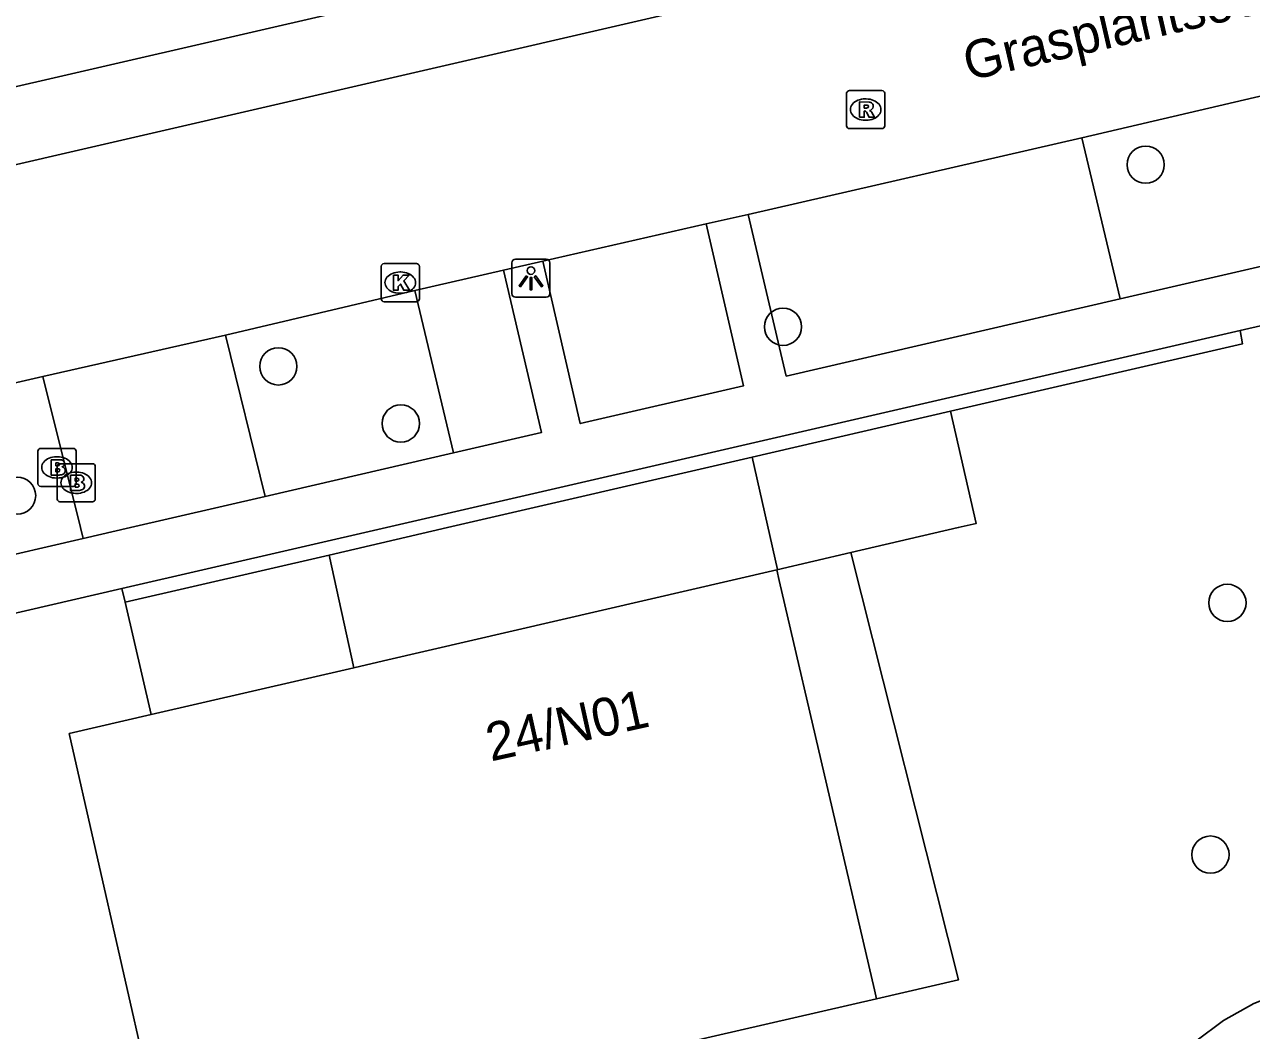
# Model space of a CAD drawing. Extents: x 156414 to 157775, y 382335 to 383765.
# Drawn here: x 156810.03 to 156842.21, y 382736.81 to 382763.2 of the extents above; entities that cross this region are included whole.
import ezdxf

# ---------------------------------------------------------------- set-up
doc = ezdxf.new("R2010")
doc.units = 0
for name, color, linetype in [('IMGEO_Boom', 7, 'Continuous'), ('IMGEO_Brandkraan', 7, 'Continuous'), ('IMGEO_Groenvoorziening', 7, 'Continuous'), ('IMGEO_Kolk', 7, 'Continuous'), ('IMGEO_Lichtpunt', 7, 'Continuous'), ('IMGEO_Lijnafwatering', 7, 'Continuous'), ('IMGEO_Muur', 7, 'Continuous'), ('IMGEO_Openbare_ruimte_label', 7, 'Continuous'), ('IMGEO_Pand', 7, 'Continuous'), ('IMGEO_Pand_nummerreeks', 7, 'Continuous'), ('IMGEO_Parkeervlak_open', 7, 'Continuous'), ('IMGEO_Rijbaan_lokaal_gesloten', 7, 'Continuous'), ('IMGEO_Rioolput', 7, 'Continuous'), ('IMGEO_Voetpad_gesloten', 7, 'Continuous'), ('IMGEO_Voetpad_open', 7, 'Continuous')]:
    doc.layers.add(name, color=color, linetype=linetype)

msp = doc.modelspace()

# ---------------------------------------------------------------- linework, layer by layer
at = {"layer": 'IMGEO_Boom'}
for centre in [(156839.435, 382759.522), (156829.923, 382755.269), (156816.688, 382754.23), (156819.901, 382752.732), (156809.836, 382750.839), (156841.578, 382748.027), (156841.134, 382741.422)]:
    msp.add_circle(centre, 0.489, dxfattribs=at)
at = {"layer": 'IMGEO_Brandkraan'}
for p, q in [((156810.382, 382751.154), (156810.382, 382752.006)), ((156810.457, 382752.08), (156811.309, 382752.08)), ((156811.383, 382752.006), (156811.383, 382751.154)), ((156810.87, 382751.86), (156810.895, 382751.86)), ((156810.887, 382750.751), (156810.887, 382751.603)), ((156810.962, 382751.677), (156811.814, 382751.677)), ((156811.888, 382751.603), (156811.888, 382750.751)), ((156810.893, 382751.3), (156810.868, 382751.3)), ((156811.375, 382751.457), (156811.4, 382751.457)), ((156811.309, 382751.08), (156810.457, 382751.08)), ((156811.814, 382750.677), (156810.962, 382750.677)), ((156811.398, 382750.897), (156811.373, 382750.897))]:
    msp.add_line(p, q, dxfattribs=at)
for points in [[(156810.382, 382751.154), (156810.382, 382752.006)], [(156810.457, 382752.08), (156811.309, 382752.08)], [(156811.383, 382752.006), (156811.383, 382751.154)], [(156810.73, 382751.78), (156810.73, 382751.38), (156810.943, 382751.38)], [(156810.961, 382751.78), (156810.73, 382751.78)], [(156810.909, 382751.699), (156810.855, 382751.699), (156810.855, 382751.623)], [(156810.855, 382751.623), (156810.908, 382751.623)], [(156810.887, 382750.751), (156810.887, 382751.603)], [(156810.962, 382751.677), (156811.814, 382751.677)], [(156811.888, 382751.603), (156811.888, 382750.751)], [(156810.917, 382751.547), (156810.855, 382751.547), (156810.855, 382751.466)], [(156810.855, 382751.466), (156810.917, 382751.466)], [(156811.235, 382751.377), (156811.235, 382750.977), (156811.448, 382750.977)], [(156811.466, 382751.377), (156811.235, 382751.377)], [(156811.414, 382751.296), (156811.36, 382751.296), (156811.36, 382751.22)], [(156811.309, 382751.08), (156810.457, 382751.08)], [(156811.36, 382751.22), (156811.413, 382751.22)], [(156811.422, 382751.144), (156811.36, 382751.144), (156811.36, 382751.063)], [(156811.36, 382751.063), (156811.422, 382751.063)], [(156811.814, 382750.677), (156810.962, 382750.677)]]:
    msp.add_lwpolyline(points, dxfattribs=at)
for centre, radius, start, end in [((156810.459, 382752.004), 0.0765, 91.552, 178.448), ((156810.459, 382752.004), 0.0765, 91.552, 178.448), ((156811.307, 382752.004), 0.0765, 1.552, 88.448), ((156811.307, 382752.004), 0.0765, 1.552, 88.448), ((156810.964, 382751.601), 0.0765, 91.552, 178.448), ((156810.964, 382751.601), 0.0765, 91.552, 178.448), ((156810.91, 382751.661), 0.0379, 267.8285, 90.9355), ((156810.965, 382751.635), 0.145, 59.4692, 91.5367), ((156810.99, 382751.682), 0.0922, 285.5137, 58.1501), ((156810.995, 382751.49), 0.105, 301.3115, 78.989), ((156811.812, 382751.601), 0.0765, 1.552, 88.448), ((156811.812, 382751.601), 0.0765, 1.552, 88.448), ((156810.918, 382751.506), 0.0404, 269.8759, 90.5077), ((156810.949, 382751.631), 0.251, 268.6676, 293.5347), ((156811.415, 382751.258), 0.0379, 267.8285, 90.9355), ((156811.47, 382751.232), 0.145, 59.4692, 91.5367), ((156811.495, 382751.279), 0.0922, 285.5137, 58.1501), ((156810.459, 382751.156), 0.0765, 181.552, 268.448), ((156810.459, 382751.156), 0.0765, 181.552, 268.448), ((156811.307, 382751.156), 0.0765, 271.552, 358.448), ((156811.307, 382751.156), 0.0765, 271.552, 358.448), ((156811.423, 382751.103), 0.0404, 269.8759, 90.5077), ((156811.454, 382751.228), 0.251, 268.6676, 293.5347), ((156811.5, 382751.087), 0.105, 301.3115, 78.989), ((156810.964, 382750.753), 0.0765, 181.552, 268.448), ((156810.964, 382750.753), 0.0765, 181.552, 268.448), ((156811.812, 382750.753), 0.0765, 271.552, 358.448), ((156811.812, 382750.753), 0.0765, 271.552, 358.448)]:
    msp.add_arc(centre, radius, start, end, dxfattribs=at)
for centre, major_axis, ratio, start_param, end_param in [((156810.869, 382751.58), (-0.387, 0.002), 0.722429, 4.712389, 7.853982), ((156810.894, 382751.58), (-0.39, 0.002), 0.717154, 1.570796, 4.712389), ((156811.374, 382751.177), (-0.387, 0.002), 0.722429, 4.712389, 7.853982), ((156811.399, 382751.177), (-0.39, 0.002), 0.717154, 1.570796, 4.712389)]:
    msp.add_ellipse(centre, major_axis=major_axis, ratio=ratio, start_param=start_param, end_param=end_param, dxfattribs=at)
at = {"layer": 'IMGEO_Groenvoorziening'}
msp.add_lwpolyline([(156834.402, 382729.53), (156839.533, 382735.185), (156840.097, 382735.898), (156840.749, 382736.531), (156841.48, 382737.073), (156842.275, 382737.513), (156843.121, 382737.845), (156844.003, 382738.064), (156844.907, 382738.164), (156845.816, 382738.144), (156846.714, 382738.005), (156847.586, 382737.749), (156848.417, 382737.38), (156848.772, 382737.18), (156853.317, 382735.569), (156854.742, 382736.058), (156854.968, 382736.079), (156855.174, 382735.984), (156855.325, 382735.725), (156855.67, 382734.37)], dxfattribs=at)
at = {"layer": 'IMGEO_Kolk'}
for p, q in [((156819.385, 382756.001), (156819.385, 382756.853)), ((156819.46, 382756.927), (156820.312, 382756.927)), ((156819.873, 382756.707), (156819.898, 382756.707)), ((156820.386, 382756.853), (156820.386, 382756.001)), ((156819.896, 382756.147), (156819.871, 382756.147)), ((156820.312, 382755.927), (156819.46, 382755.927))]:
    msp.add_line(p, q, dxfattribs=at)
for points in [[(156819.385, 382756.001), (156819.385, 382756.853)], [(156819.46, 382756.927), (156820.312, 382756.927)], [(156820.386, 382756.853), (156820.386, 382756.001)], [(156819.706, 382756.627), (156819.829, 382756.627), (156819.829, 382756.476), (156819.959, 382756.627), (156820.123, 382756.627), (156819.977, 382756.476), (156820.13, 382756.227), (156819.978, 382756.227), (156819.893, 382756.391), (156819.829, 382756.324), (156819.829, 382756.227), (156819.706, 382756.227), (156819.706, 382756.627)], [(156820.312, 382755.927), (156819.46, 382755.927)]]:
    msp.add_lwpolyline(points, dxfattribs=at)
for centre, start, end in [((156819.462, 382756.851), 91.552, 178.448), ((156819.462, 382756.851), 91.552, 178.448), ((156820.31, 382756.851), 1.552, 88.448), ((156820.31, 382756.851), 1.552, 88.448), ((156819.462, 382756.003), 181.552, 268.448), ((156819.462, 382756.003), 181.552, 268.448), ((156820.31, 382756.003), 271.552, 358.448), ((156820.31, 382756.003), 271.552, 358.448)]:
    msp.add_arc(centre, 0.0765, start, end, dxfattribs=at)
for centre, major_axis, ratio, start_param, end_param in [((156819.872, 382756.427), (-0.387, 0.002), 0.722429, 4.712389, 7.853982), ((156819.897, 382756.427), (-0.39, 0.002), 0.717154, 1.570796, 4.712389)]:
    msp.add_ellipse(centre, major_axis=major_axis, ratio=ratio, start_param=start_param, end_param=end_param, dxfattribs=at)
at = {"layer": 'IMGEO_Lichtpunt'}
for p, q in [((156823.716, 382757.041), (156822.908, 382757.041)), ((156823.716, 382757.041), (156822.908, 382757.041)), ((156822.814, 382756.946), (156822.814, 382756.139)), ((156822.814, 382756.946), (156822.814, 382756.139)), ((156823.81, 382756.139), (156823.81, 382756.946)), ((156823.81, 382756.139), (156823.81, 382756.946)), ((156822.908, 382756.045), (156823.716, 382756.045)), ((156822.908, 382756.045), (156823.716, 382756.045))]:
    msp.add_line(p, q, dxfattribs=at)
for points in [[(156823.188, 382756.61), (156823.227, 382756.582), (156823.039, 382756.32), (156823.001, 382756.347), (156823.188, 382756.61)], [(156823.29, 382756.562), (156823.337, 382756.562), (156823.337, 382756.24), (156823.29, 382756.24), (156823.29, 382756.562)], [(156823.4, 382756.582), (156823.438, 382756.609), (156823.625, 382756.347), (156823.586, 382756.319), (156823.4, 382756.582)]]:
    msp.add_lwpolyline(points, dxfattribs=at)
msp.add_circle((156823.313, 382756.744), 0.0994, dxfattribs=at)
for centre, start, end in [((156822.908, 382756.946), 90, 180), ((156822.908, 382756.946), 90, 180), ((156823.716, 382756.946), 0, 90), ((156823.716, 382756.946), 0, 90), ((156822.908, 382756.139), 180, 270), ((156822.908, 382756.139), 180, 270), ((156823.716, 382756.139), 270, 0), ((156823.716, 382756.139), 270, 360)]:
    msp.add_arc(centre, 0.0946, start, end, dxfattribs=at)
at = {"layer": 'IMGEO_Lijnafwatering'}
for points in [[(156829.117, 382751.849), (156829.775, 382748.901)], [(156818.017, 382749.281), (156818.667, 382746.326)]]:
    msp.add_lwpolyline(points, dxfattribs=at)
at = {"layer": 'IMGEO_Muur'}
for points in [[(156841.91, 382755.169), (156819.521, 382750), (156812.585, 382748.399)], [(156834.315, 382753.052), (156841.976, 382754.824), (156841.91, 382755.169)], [(156812.67, 382748.044), (156818.017, 382749.281), (156821.124, 382750), (156829.117, 382751.849), (156834.315, 382753.052)], [(156812.585, 382748.399), (156812.67, 382748.044)]]:
    msp.add_lwpolyline(points, dxfattribs=at)
at = {"layer": 'IMGEO_Pand'}
for points in [[(156829.759, 382748.897), (156819.447, 382746.507), (156818.667, 382746.326), (156813.35, 382745.095)], [(156832.373, 382737.642), (156832.32, 382737.871), (156829.826, 382748.61), (156829.759, 382748.897)], [(156813.35, 382745.095), (156811.203, 382744.597), (156813.271, 382735.473), (156813.741, 382733.355), (156832.373, 382737.642)]]:
    msp.add_lwpolyline(points, dxfattribs=at)
at = {"layer": 'IMGEO_Parkeervlak_open'}
for points in [[(156838.766, 382756.004), (156837.759, 382760.224)], [(156820.266, 382756.217), (156821.286, 382751.96)], [(156815.301, 382755.052), (156816.346, 382750.817)], [(156811.571, 382749.713), (156811.5, 382750), (156810.513, 382753.968)]]:
    msp.add_lwpolyline(points, dxfattribs=at)
at = {"layer": 'IMGEO_Rijbaan_lokaal_gesloten'}
for points in [[(156721.265, 382739.07), (156830.11, 382764.227), (156940.449, 382789.73)], [(156837.759, 382760.224), (156846.29, 382762.216)], [(156829.006, 382758.219), (156837.759, 382760.224)], [(156827.904, 382757.967), (156829.006, 382758.219)], [(156823.627, 382756.987), (156827.904, 382757.967)], [(156820.266, 382756.217), (156822.595, 382756.751)], [(156822.595, 382756.751), (156823.627, 382756.987)], [(156815.301, 382755.052), (156820.266, 382756.217)], [(156810.513, 382753.968), (156815.301, 382755.052)], [(156804.584, 382752.601), (156810.513, 382753.968)]]:
    msp.add_lwpolyline(points, dxfattribs=at)
at = {"layer": 'IMGEO_Rioolput'}
for p, q in [((156831.591, 382760.542), (156831.591, 382761.394)), ((156831.666, 382761.468), (156832.518, 382761.468)), ((156832.079, 382761.248), (156832.104, 382761.248)), ((156832.592, 382761.394), (156832.592, 382760.542)), ((156832.102, 382760.688), (156832.077, 382760.688)), ((156832.518, 382760.468), (156831.666, 382760.468))]:
    msp.add_line(p, q, dxfattribs=at)
for points in [[(156831.591, 382760.542), (156831.591, 382761.394)], [(156831.666, 382761.468), (156832.518, 382761.468)], [(156832.592, 382761.394), (156832.592, 382760.542)], [(156832.18, 382761.166), (156831.928, 382761.168), (156831.928, 382760.768)], [(156831.928, 382760.768), (156832.052, 382760.768), (156832.052, 382760.93), (156832.063, 382760.93)], [(156832.106, 382761.087), (156832.052, 382761.087), (156832.052, 382761.006)], [(156832.052, 382761.006), (156832.104, 382761.006)], [(156832.11, 382760.901), (156832.181, 382760.768), (156832.321, 382760.768), (156832.256, 382760.894)], [(156832.518, 382760.468), (156831.666, 382760.468)]]:
    msp.add_lwpolyline(points, dxfattribs=at)
for centre, radius, start, end in [((156831.668, 382761.392), 0.0765, 91.552, 178.448), ((156831.668, 382761.392), 0.0765, 91.552, 178.448), ((156832.516, 382761.392), 0.0765, 1.552, 88.448), ((156832.516, 382761.392), 0.0765, 1.552, 88.448), ((156832.062, 382760.877), 0.0533, 26.0293, 88.6989), ((156832.088, 382761.195), 0.19, 274.7715, 282.9687), ((156832.112, 382760.991), 0.0964, 77.0061, 93.1865), ((156832.126, 382761.048), 0.0378, 276.6634, 79.6772), ((156832.179, 382761.056), 0.109, 350.3612, 89.416), ((156832.177, 382761.056), 0.112, 277.5842, 350.9817), ((156832.161, 382760.841), 0.108, 29.5134, 73.7905), ((156831.668, 382760.544), 0.0765, 181.552, 268.448), ((156831.668, 382760.544), 0.0765, 181.552, 268.448), ((156832.516, 382760.544), 0.0765, 271.552, 358.448), ((156832.516, 382760.544), 0.0765, 271.552, 358.448)]:
    msp.add_arc(centre, radius, start, end, dxfattribs=at)
for centre, major_axis, ratio, start_param, end_param in [((156832.078, 382760.968), (-0.387, 0.002), 0.722429, 4.712389, 7.853982), ((156832.103, 382760.968), (-0.39, 0.002), 0.717154, 1.570796, 4.712389)]:
    msp.add_ellipse(centre, major_axis=major_axis, ratio=ratio, start_param=start_param, end_param=end_param, dxfattribs=at)
at = {"layer": 'IMGEO_Voetpad_gesloten'}
for points in [[(156831.699, 382749.347), (156829.759, 382748.897)], [(156831.699, 382749.347), (156834.527, 382738.137), (156832.373, 382737.642)]]:
    msp.add_lwpolyline(points, dxfattribs=at)
at = {"layer": 'IMGEO_Voetpad_open'}
for points in [[(156865.597, 382774.441), (156795.182, 382758.201)], [(156829.006, 382758.219), (156830.007, 382753.978), (156838.766, 382756.004)], [(156823.627, 382756.987), (156824.606, 382752.728), (156828.884, 382753.718), (156827.904, 382757.967)], [(156821.286, 382751.96), (156823.587, 382752.492), (156822.595, 382756.751)], [(156838.766, 382756.004), (156843.161, 382757.021)], [(156841.91, 382755.169), (156846.252, 382756.171)], [(156834.315, 382753.052), (156834.992, 382750.11), (156834.518, 382750), (156831.699, 382749.347)], [(156816.346, 382750.817), (156821.286, 382751.96)], [(156816.346, 382750.817), (156812.812, 382750), (156811.571, 382749.713)], [(156805.537, 382748.317), (156806.026, 382748.43), (156808.846, 382749.082), (156811.571, 382749.713)], [(156806.778, 382747.058), (156807.635, 382747.256), (156812.585, 382748.399)], [(156813.35, 382745.095), (156812.67, 382748.044)]]:
    msp.add_lwpolyline(points, dxfattribs=at)

# ---------------------------------------------------------------- texts
at = {"layer": 'IMGEO_Openbare_ruimte_label'}
msp.add_text('Grasplantsoen', height=1, rotation=13.0075, dxfattribs=at).set_placement((156834.785, 382761.721))
at = {"layer": 'IMGEO_Pand_nummerreeks'}
msp.add_text('24/N01', height=1, rotation=12.4415, dxfattribs=at).set_placement((156822.261, 382743.863))

doc.saveas('drawing.dxf')
